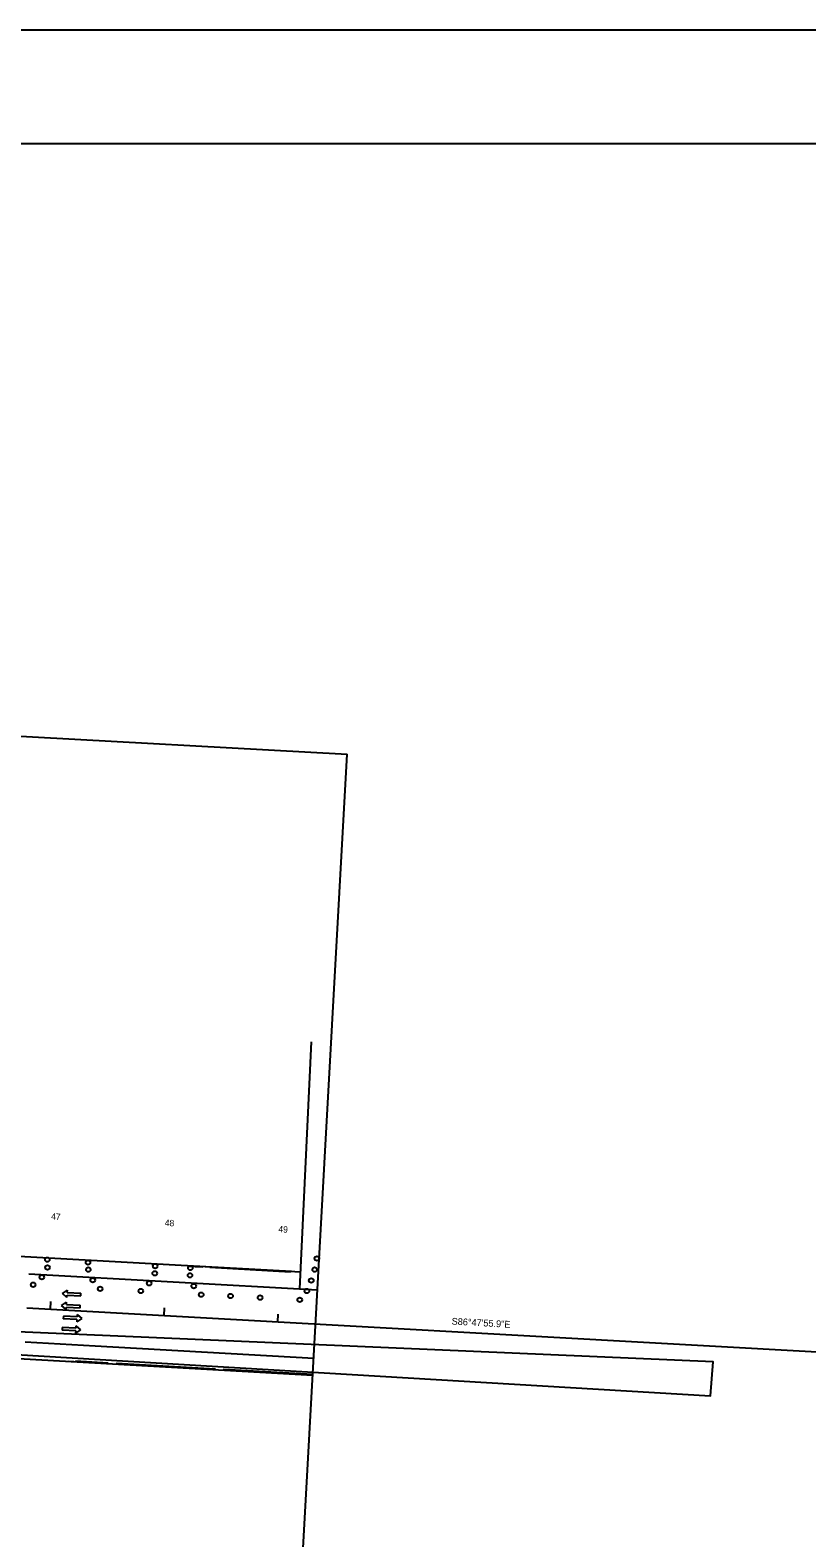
# Model space of a CAD drawing. Extents: x 679444 to 687671, y 733868 to 736107.
# Drawn here: x 683958 to 684641, y 734782 to 736107 of the extents above; entities that cross this region are included whole.
import ezdxf

# ---------------------------------------------------------------- set-up
doc = ezdxf.new("R2010")
doc.units = 0
for name, color, linetype in [('$', 7, 'Continuous'), ('border All Plan 20-40_Border 3 - Level 1', 7, 'Continuous'), ('C-TOPO', 7, 'Continuous'), ('C-TOPO-FEAT', 7, 'Continuous'), ('Clipping Boundary', 7, 'Continuous'), ('MOT Stage 1', 7, 'Continuous'), ('R_Horz Alg Station', 7, 'Continuous'), ('R_TYPE_A_CURB', 7, 'Continuous'), ('RW-EX', 7, 'Continuous'), ('RW-PR', 7, 'Continuous'), ('V-NODE', 7, 'Continuous')]:
    doc.layers.add(name, color=color, linetype=linetype)

# ---------------------------------------------------------------- blocks, each defined once
blk = doc.blocks.new('BAREL_1619')
at = {"layer": 'MOT Stage 1'}
blk.add_circle((0, 0), 2.88, dxfattribs=at)
blk = doc.blocks.new('BAREL_1620')
at = {"layer": 'MOT Stage 1'}
blk.add_circle((0, 0), 2.88, dxfattribs=at)
blk = doc.blocks.new('BAREL_1621')
at = {"layer": 'MOT Stage 1'}
blk.add_circle((0, 0), 2.88, dxfattribs=at)
blk = doc.blocks.new('BAREL_1622')
at = {"layer": 'MOT Stage 1'}
blk.add_circle((0, 0), 2.88, dxfattribs=at)
blk = doc.blocks.new('BAREL_1623')
at = {"layer": 'MOT Stage 1'}
blk.add_circle((0, 0), 2.88, dxfattribs=at)
blk = doc.blocks.new('BAREL_1624')
at = {"layer": 'MOT Stage 1'}
blk.add_circle((0, 0), 2.88, dxfattribs=at)
blk = doc.blocks.new('BAREL_1625')
at = {"layer": 'MOT Stage 1'}
blk.add_circle((0, 0), 2.88, dxfattribs=at)
blk = doc.blocks.new('BAREL_1626')
at = {"layer": 'MOT Stage 1'}
blk.add_circle((0, 0), 2.88, dxfattribs=at)
blk = doc.blocks.new('BAREL_1628')
at = {"layer": 'MOT Stage 1'}
blk.add_circle((0, 0), 2.88, dxfattribs=at)
blk = doc.blocks.new('BAREL_1629')
at = {"layer": 'MOT Stage 1'}
blk.add_circle((0, 0), 2.88, dxfattribs=at)
blk = doc.blocks.new('BAREL_1630')
at = {"layer": 'MOT Stage 1'}
blk.add_circle((0, 0), 2.88, dxfattribs=at)
blk = doc.blocks.new('SARROW_199')
at = {"layer": 'MOT Stage 1'}
for p, q in [((0, 0), (-6, 0)), ((0, -29.4), (0, 0)), ((-6, -29.4), (-11, -29.4)), ((-3, -39.8), (-11, -29.4)), ((-6, -29.4), (-6, 0)), ((5, -29.4), (-3, -39.8)), ((5, -29.4), (0, -29.4))]:
    blk.add_line(p, q, dxfattribs=at)
blk = doc.blocks.new('SARROW_200')
at = {"layer": 'MOT Stage 1'}
for p, q in [((0, 0), (-6, 0)), ((0, -29.4), (0, 0)), ((-6, -29.4), (-11, -29.4)), ((-3, -39.8), (-11, -29.4)), ((-6, -29.4), (-6, 0)), ((5, -29.4), (-3, -39.8)), ((5, -29.4), (0, -29.4))]:
    blk.add_line(p, q, dxfattribs=at)
blk = doc.blocks.new('SARROW_201')
at = {"layer": 'MOT Stage 1'}
for p, q in [((0, 0), (-6, 0)), ((0, -29.4), (0, 0)), ((-6, -29.4), (-11, -29.4)), ((-3, -39.8), (-11, -29.4)), ((-6, -29.4), (-6, 0)), ((5, -29.4), (-3, -39.8)), ((5, -29.4), (0, -29.4))]:
    blk.add_line(p, q, dxfattribs=at)
blk = doc.blocks.new('SARROW_202')
at = {"layer": 'MOT Stage 1'}
for p, q in [((0, 0), (-6, 0)), ((0, -29.4), (0, 0)), ((-6, -29.4), (-11, -29.4)), ((-3, -39.8), (-11, -29.4)), ((-6, -29.4), (-6, 0)), ((5, -29.4), (-3, -39.8)), ((5, -29.4), (0, -29.4))]:
    blk.add_line(p, q, dxfattribs=at)
blk = doc.blocks.new('BAREL_1691')
at = {"layer": 'MOT Stage 1'}
blk.add_circle((0, 0), 2.88, dxfattribs=at)
blk = doc.blocks.new('BAREL_1692')
at = {"layer": 'MOT Stage 1'}
blk.add_circle((0, 0), 2.88, dxfattribs=at)
blk = doc.blocks.new('BAREL_1694')
at = {"layer": 'MOT Stage 1'}
blk.add_circle((0, 0), 2.88, dxfattribs=at)
blk = doc.blocks.new('BAREL_1695')
at = {"layer": 'MOT Stage 1'}
blk.add_circle((0, 0), 2.88, dxfattribs=at)
blk = doc.blocks.new('BAREL_1696')
at = {"layer": 'MOT Stage 1'}
blk.add_circle((0, 0), 2.88, dxfattribs=at)
blk = doc.blocks.new('BAREL_1697')
at = {"layer": 'MOT Stage 1'}
blk.add_circle((0, 0), 2.88, dxfattribs=at)
blk = doc.blocks.new('BAREL_1698')
at = {"layer": 'MOT Stage 1'}
blk.add_circle((0, 0), 2.88, dxfattribs=at)
blk = doc.blocks.new('BAREL_1699')
at = {"layer": 'MOT Stage 1'}
blk.add_circle((0, 0), 2.88, dxfattribs=at)
blk = doc.blocks.new('BAREL_1700')
at = {"layer": 'MOT Stage 1'}
blk.add_circle((0, 0), 2.88, dxfattribs=at)
blk = doc.blocks.new('BAREL_1701')
at = {"layer": 'MOT Stage 1'}
blk.add_circle((0, 0), 2.88, dxfattribs=at)
blk = doc.blocks.new('BAREL_1702')
at = {"layer": 'MOT Stage 1'}
blk.add_circle((0, 0), 2.88, dxfattribs=at)
blk = doc.blocks.new('BAREL_1703')
at = {"layer": 'MOT Stage 1'}
blk.add_circle((0, 0), 2.88, dxfattribs=at)

msp = doc.modelspace()

# ---------------------------------------------------------------- linework, layer by layer
at = {"layer": '$'}
msp.add_lwpolyline([(679553.9, 733968.3), (687571.1, 733968.3), (687571.1, 736006.7), (679553.9, 736006.7), (679553.9, 733968.3)], dxfattribs=at)
at = {"layer": 'border All Plan 20-40_Border 3 - Level 1'}
for p in [(682658.2, 735557.9), (684179.8, 734444.7)]:
    msp.add_line(p, (684236.6, 735470.4), dxfattribs=at)
at = {"layer": 'C-TOPO'}
msp.add_lwpolyline([(679453.9, 733868.3), (687671.1, 733868.3), (687671.1, 736106.7), (679453.9, 736106.7), (679453.9, 733868.3)], dxfattribs=at)
at = {"layer": 'C-TOPO-FEAT'}
msp.add_lwpolyline([(679553.9, 733968.3), (687571.1, 733968.3), (687571.1, 736006.7), (679553.9, 736006.7), (679553.9, 733968.3)], dxfattribs=at)
at = {"layer": 'Clipping Boundary'}
msp.add_lwpolyline([(683681.2, 734974.2), (683679.4, 734958.5), (684556, 734906.4), (684558.4, 734936.2)], close=True, dxfattribs=at)
at = {"layer": 'R_Horz Alg Station'}
msp.add_line((683955.1, 734983.8), (684762.2, 734938.7), dxfattribs=at)
for points in [[(683975.8, 734989.3), (683975.5, 734982.7)], [(684075.7, 734983.7), (684075.3, 734977.1)], [(684175.5, 734978.1), (684175.2, 734971.5)]]:
    msp.add_lwpolyline(points, dxfattribs=at)
at = {"layer": 'R_TYPE_A_CURB'}
for p, q in [((684096.3, 735021), (684187.5, 735015.9)), ((684096.3, 735020.5), (684109.7, 735019.7)), ((684115.7, 735019.4), (684186.7, 735015.4)), ((684026.4, 734934.7), (683991.4, 734936.7)), ((684026.4, 734935.2), (683997.7, 734936.8)), ((684120.7, 734930), (684033.4, 734934.8)), ((684120.7, 734929.5), (684033.4, 734934.3)), ((684206.4, 734925.2), (684127.7, 734929.6)), ((684206.4, 734924.7), (684127.7, 734929.1))]:
    msp.add_line(p, q, dxfattribs=at)
at = {"layer": 'RW-EX'}
for p, q in [((684195, 735000.4), (684205.3, 735217.5)), ((683956.8, 735013.7), (684210.6, 734999.5)), ((683953.5, 734953.8), (684015, 734950.4)), ((684015, 734950.4), (684207.2, 734939.6))]:
    msp.add_line(p, q, dxfattribs=at)
at = {"layer": 'RW-PR'}
for points in [[(683664.3, 735060.1), (683703.4, 735042.9), (683910.6, 735031.3), (684095.9, 735021), (684195.7, 735015.4)], [(683648.2, 734950.9), (683683.5, 734956.4), (683823.3, 734948.6), (683952.6, 734938.9), (684206.4, 734924.7)]]:
    msp.add_lwpolyline(points, dxfattribs=at)
at = {"layer": 'V-NODE'}
msp.add_lwpolyline([(679553.9, 733968.3), (687571.1, 733968.3), (687571.1, 736006.7), (679553.9, 736006.7), (679553.9, 733968.3)], dxfattribs=at)

# ---------------------------------------------------------------- block references
at = {"layer": 'MOT Stage 1'}
for name, p, xscale, yscale, rotation in [('BAREL_1619', (683973, 735026.1), 0.6945420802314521, 0.6945420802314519, 87.04179557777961), ('BAREL_1628', (684210, 735027.2), 0.6945420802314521, 0.6945420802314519, 87.04179557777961), ('BAREL_1623', (683973.1, 735019.3), 0.6945420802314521, 0.6945420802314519, 87.04179557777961), ('BAREL_1621', (684008.7, 735023.6), 0.6945420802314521, 0.6945420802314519, 87.04179557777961), ('BAREL_1624', (684009, 735017.4), 0.6945420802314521, 0.6945420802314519, 87.04179557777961), ('BAREL_1625', (684067.4, 735014.1), 0.6945420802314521, 0.6945420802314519, 87.04179557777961), ('BAREL_1620', (684067.8, 735020.5), 0.6945420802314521, 0.6945420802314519, 87.04179557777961), ('BAREL_1626', (684098.4, 735012.4), 0.6945420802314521, 0.6945420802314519, 87.04179557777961), ('BAREL_1622', (684098.7, 735018.8), 0.6945420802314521, 0.6945420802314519, 87.04179557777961), ('BAREL_1629', (684208, 735017.4), 0.6945420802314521, 0.6945420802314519, 87.04179557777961), ('BAREL_1692', (683960.5, 735004.1), 0.6945420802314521, 0.6945420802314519, 87.04179557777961), ('BAREL_1691', (683968.1, 735010.7), 0.6945420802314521, 0.6945420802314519, 87.04179557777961), ('BAREL_1694', (684012.9, 735008.1), 0.6945420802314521, 0.6945420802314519, 87.04179557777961), ('BAREL_1695', (684019.4, 735000.5), 0.6945420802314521, 0.6945420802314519, 87.04179557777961), ('BAREL_1697', (684055.2, 734998.6), 0.6945420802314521, 0.6945420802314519, 87.04179557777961), ('BAREL_1696', (684062.5, 735005.4), 0.6945420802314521, 0.6945420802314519, 87.04179557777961), ('BAREL_1698', (684101.7, 735002.9), 0.6945420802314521, 0.6945420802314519, 87.04179557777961), ('BAREL_1700', (684201.2, 734998.6), 0.6945420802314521, 0.6945420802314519, 87.04179557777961), ('BAREL_1630', (684205, 735007.8), 0.6945420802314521, 0.6945420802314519, 87.04179557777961), ('SARROW_202', (684001.7, 734983.7), 0.40758735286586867, 0.4075873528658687, -93.0312882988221), ('SARROW_201', (684002.3, 734994.3), 0.40758735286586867, 0.4075873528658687, -93.0312882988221), ('BAREL_1699', (684108.3, 734995.4), 0.6945420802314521, 0.6945420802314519, 87.04179557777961), ('BAREL_1703', (684134.1, 734994.2), 0.6945420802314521, 0.6945420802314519, 87.04179557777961), ('BAREL_1702', (684160, 734992.8), 0.6945420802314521, 0.6945420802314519, 87.04179557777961), ('BAREL_1701', (684194.9, 734990.8), 0.6945420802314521, 0.6945420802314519, 87.04179557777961), ('SARROW_199', (683987.1, 734976.6), 0.40758735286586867, 0.4075873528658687, 86.96871170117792), ('SARROW_200', (683986.1, 734966.6), 0.40758735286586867, 0.4075873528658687, 86.96871170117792)]:
    msp.add_blockref(name, p, dxfattribs=dict(at, xscale=xscale, yscale=yscale, rotation=rotation))

# ---------------------------------------------------------------- texts
at = {"layer": '$'}
for s, p in [('47', (683976.2, 735061.4)), ('48', (684076.1, 735055.8)), ('49', (684176, 735050.2))]:
    msp.add_text(s, height=5.6, rotation=357.0415, dxfattribs=at).set_placement(p)
at = {"layer": 'R_Horz Alg Station'}
msp.add_text('S86%%d47\'55.9"E', height=6, rotation=356.7989, dxfattribs=at).set_placement((684328.3, 734969.1))

doc.saveas('drawing.dxf')
